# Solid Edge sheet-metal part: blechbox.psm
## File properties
Author: Administrator
Template: Normal.psm
Last saved by: Administrator
Revision: 2
Application: Solid Edge
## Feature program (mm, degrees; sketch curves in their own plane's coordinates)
base tab "unnamed BaseTab 1"
contour flange "unnamed ContourFlange 1"
